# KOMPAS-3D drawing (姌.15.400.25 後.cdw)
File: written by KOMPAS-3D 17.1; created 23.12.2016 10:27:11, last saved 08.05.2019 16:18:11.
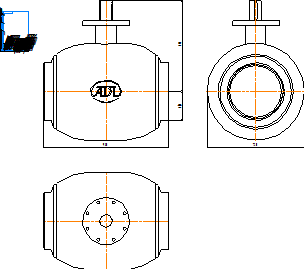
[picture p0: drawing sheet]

Sheet 1: A4, portrait

Title block, sheet 1: name: КШ.15.400.25 сс; material: Внимание! Данный продукт является объектом авторского права ООО «Торговый Дом АДЛ». / Запрещается изменение, копирование, распространение / (в том числе путем копирования на другие сайты и ресурсы в Интернете) / или любое иное использование информации и объектов без предварительного / согласия правообладателя (ООО «Торговый Дом АДЛ»).; sheets: 1; organisation: ООО "Торговый дом АДЛ"; sheet format: A4; stored path: C:\Users\tra\Desktop\2д чертежи\Шаровые краны БИВАЛ\КШ_Бивал_серия_14_15\KOMPAS_2D\КШ.15.400.25 сс.cdw

Views: Вид 1, Проекционный вид 2, Проекционный вид 3
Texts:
  Klimkovich
  ADL
Dimensions and other numbers on the sheet: 930; 673; 213; 720; 1:1; 1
